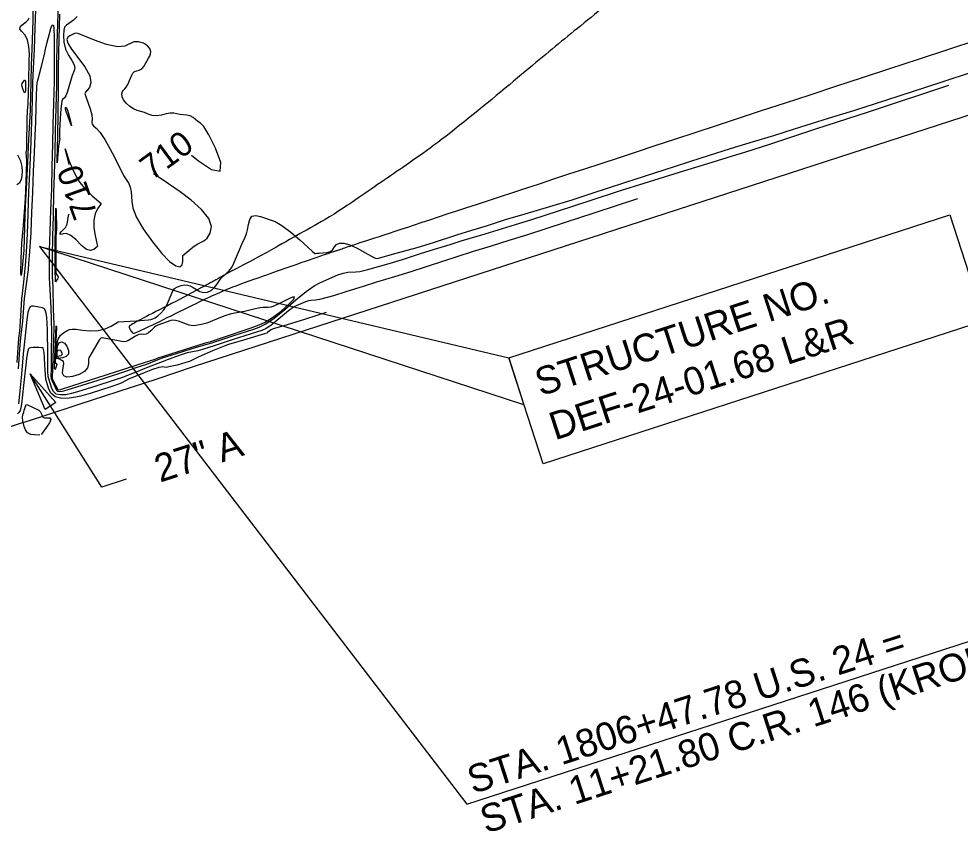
# Model space of a CAD drawing. Extents: x -468541894 to 3393103, y -306086142 to 1227927.
# Drawn here: x 1845797 to 1847065, y 538248 to 539346 of the extents above; entities that cross this region are included whole.
import ezdxf

# ---------------------------------------------------------------- set-up
doc = ezdxf.new("R2010")
doc.units = 0
for name, color, linetype in [('DT_X_Contour_Minor', 7, 'Continuous'), ('Level 14', 7, 'Continuous'), ('Level 19', 7, 'Continuous'), ('Level 25', 7, 'Continuous'), ('Level 40', 7, 'Continuous')]:
    doc.layers.add(name, color=color, linetype=linetype)

msp = doc.modelspace()

# ---------------------------------------------------------------- linework, layer by layer
at = {"layer": 'DT_X_Contour_Minor'}
for points in [[(1845796.1, 539631.5), (1845814.6, 539657.1), (1845822.7, 539667.7), (1845827.1, 539671.5), (1845828.6, 539670.1), (1845828.6, 539666.3), (1845827.1, 539640.6), (1845825.6, 539618.4), (1845823.8, 539591.3), (1845822.3, 539563.4), (1845821.5, 539536.7), (1845820.2, 539505.2), (1845818.8, 539476.1), (1845818.5, 539455), (1845817.9, 539424.5), (1845817.2, 539407), (1845816, 539372.8), (1845815.2, 539345), (1845814.3, 539317.6), (1845813.1, 539283.3), (1845812.5, 539261.9), (1845811.7, 539224.5), (1845811.3, 539214.9)], [(1845849.4, 539368.3), (1845848.6, 539339.2), (1845847.9, 539313.8), (1845847.2, 539285.2), (1845847.1, 539256.6), (1845846.4, 539226.7), (1845845.7, 539194.5), (1845845, 539166.5), (1845844, 539136.2), (1845843.3, 539111.8), (1845842.6, 539080.6), (1845841.7, 539053.3), (1845841.5, 539025.6), (1845841.6, 538998.3), (1845842.3, 538984.9), (1845843, 538954.3), (1845843.5, 538935.1), (1845843.6, 538928.7), (1845843.2, 538915.2), (1845842.3, 538889.5), (1845842.1, 538874.3), (1845841.6, 538862.2), (1845841.9, 538860.4), (1845842.8, 538858.3), (1845848.9, 538846.4), (1845849.4, 538846), (1845850.2, 538846), (1845852.9, 538846.7), (1845869.1, 538851.8), (1845901.8, 538862.4), (1845928.1, 538870.7), (1845957.4, 538880.1), (1845980.1, 538887.6), (1845984.2, 538889.2), (1846010, 538897.4), (1846048, 538909.3), (1846055.2, 538911.5), (1846072.5, 538917.3), (1846106.9, 538928.7), (1846118.2, 538932.7), (1846127.6, 538937), (1846138.6, 538943.5), (1846150.3, 538952.4), (1846160.5, 538961.6), (1846167, 538968.6), (1846168.1, 538971.4), (1846165.2, 538971), (1846160.4, 538968.9), (1846146.2, 538961.7), (1846139.1, 538958.3)], [(1845810.9, 539130.3), (1845812.1, 539159.2), (1845813, 539180.8), (1845814.2, 539208.3), (1845815.1, 539236.4), (1845815.5, 539260), (1845816.3, 539279.4), (1845817.6, 539305.3), (1845818.6, 539334), (1845819.4, 539359.1)], [(1845811.3, 539214.9), (1845809.6, 539183.7), (1845808.1, 539153.2), (1845806.7, 539126.1), (1845805.2, 539093.5), (1845804.3, 539065.8), (1845803.1, 539034.5), (1845800.4, 539006), (1845799.5, 539000.4), (1845799.3, 539003.9), (1845799.8, 539022.7), (1845800.8, 539044), (1845802.7, 539067.8), (1845805.4, 539104.3), (1845806.3, 539126.4), (1845807.1, 539154), (1845807, 539161.5), (1845806.4, 539165.9), (1845806.3, 539167), (1845806.9, 539167.8), (1845807.2, 539170), (1845807.5, 539176), (1845807.9, 539211), (1845808.3, 539222.5), (1845808.9, 539232), (1845809.9, 539261.3), (1845810.6, 539290.2), (1845810.7, 539298.9), (1845810.1, 539308.9), (1845808.1, 539318.1), (1845804.4, 539324.7), (1845800.4, 539329.2), (1845797.8, 539332.5), (1845798.2, 539335.3), (1845800.6, 539338), (1845806.7, 539342.7), (1845809, 539345.1), (1845810.6, 539347.9)], [(1845875.3, 539349.6), (1845870.2, 539344.7), (1845860.6, 539337.8), (1845858.3, 539335.2), (1845857.1, 539331), (1845856.6, 539323.9), (1845857.2, 539315), (1845859.5, 539305.7), (1845863.5, 539297.3), (1845868, 539290.1), (1845871.1, 539284.4), (1845871.8, 539279.8), (1845870.5, 539275.5), (1845868.3, 539270), (1845866, 539262.5), (1845861.8, 539247.3), (1845859.9, 539242.6), (1845858.2, 539240), (1845855.5, 539237.6), (1845854.5, 539235.2), (1845853.5, 539229.3), (1845852.6, 539219), (1845851.3, 539196), (1845851.5, 539186), (1845851.6, 539184.6), (1845850.2, 539175.3), (1845848.1, 539152.3), (1845848.1, 539156.4), (1845849, 539188), (1845849.5, 539218.5), (1845850, 539252.1), (1845850.1, 539281.8), (1845850.4, 539300.1), (1845850.9, 539319.5), (1845852, 539352.7)], [(1845796.2, 538874.3), (1845798.5, 538907.4), (1845799.9, 538920.4), (1845801.7, 538938.8), (1845804.1, 538969.3), (1845805.8, 538982.5), (1845809.4, 539008.1), (1845810.1, 539016.3), (1845811.3, 539032.7), (1845812.4, 539045.3), (1845813.2, 539058.5), (1845814, 539085.7), (1845815.3, 539112.4), (1845816.4, 539141.1), (1845817.5, 539165.5), (1845818.6, 539189.4), (1845819.5, 539207.2), (1845819.9, 539228.2), (1845821, 539255.4), (1845821.9, 539262.4), (1845823.4, 539268.2), (1845824.6, 539272.1), (1845826.7, 539280.7), (1845831.3, 539298.3), (1845832.7, 539305.4), (1845834.2, 539313.2), (1845839.2, 539331.5), (1845839.7, 539333.6), (1845840.7, 539335.9), (1845841.8, 539337.7), (1845842.8, 539338.4), (1845843.3, 539337.5), (1845843.6, 539333.4), (1845844, 539321.3), (1845844.3, 539308.9), (1845844.2, 539293.2), (1845844.2, 539280.8), (1845844.1, 539261.4), (1845843.3, 539232.9), (1845842.5, 539203.5), (1845841.8, 539177.4), (1845841.1, 539147.1), (1845840.4, 539117.2), (1845839.3, 539088.2), (1845838.1, 539059.8), (1845837.5, 539034.3), (1845837.2, 539007.7), (1845837.6, 538997.1), (1845838.9, 538973.3), (1845839.5, 538956.5), (1845840.3, 538940.1), (1845840.7, 538924.8), (1845840, 538894.2), (1845839.9, 538875.7), (1845839.7, 538864), (1845840, 538861.6), (1845840.8, 538859.2), (1845847.1, 538845.5), (1845848.6, 538844.2), (1845851, 538843.7), (1845855.2, 538844.3), (1845861.8, 538846.1), (1845881.8, 538852.3), (1845910.5, 538861.6), (1845942, 538871.7), (1845954.8, 538876.2)], [(1846786.6, 539180.9), (1846814.2, 539189.3), (1846842, 539198), (1846887.9, 539212.3), (1846922.2, 539222.7), (1846965.2, 539236.6), (1847039.8, 539261), (1847127, 539289.7), (1847259.8, 539333.4)], [(1846029.2, 539162.6), (1846038.8, 539154.8), (1846056.4, 539143.4), (1846068.1, 539141.1), (1846068.7, 539152.6), (1846061.6, 539171.9), (1846052.5, 539190.2), (1846045.8, 539201.1), (1846041.3, 539205.8), (1846038, 539208.1), (1846031.4, 539213.3), (1846027.4, 539215.4), (1846022.9, 539216.5), (1846013.5, 539217.3), (1846005.4, 539219.3), (1846000.7, 539219.4), (1845995, 539218.1), (1845988.7, 539216.3), (1845982.3, 539215.4), (1845976.3, 539216.1), (1845970.8, 539218), (1845965.7, 539220), (1845956.1, 539223), (1845951.2, 539225.1), (1845946, 539228.4), (1845941.2, 539232.5), (1845937.6, 539237), (1845935.8, 539241.4), (1845935.5, 539245.2), (1845936.3, 539248.3), (1845937.6, 539250.3), (1845939.4, 539252), (1845941.4, 539254.3), (1845943.4, 539257.8), (1845947.2, 539266.4), (1845948.7, 539270.3), (1845950.4, 539273.3), (1845952.6, 539275.4), (1845955.5, 539276.5), (1845958.9, 539277.3), (1845962.2, 539279), (1845965, 539282.1), (1845971.5, 539293.3), (1845973, 539296.1), (1845974.1, 539299), (1845974.3, 539302.4), (1845973.1, 539306.2), (1845970, 539310.1), (1845964.5, 539313.5), (1845957.9, 539315.6), (1845951.4, 539315.5), (1845939.3, 539309.5), (1845929.5, 539308.6), (1845914.9, 539312), (1845898.7, 539317.8), (1845877.4, 539326.2), (1845873.8, 539327), (1845871.7, 539326.5), (1845868.7, 539325.4), (1845865.4, 539323.7), (1845862.6, 539321.5), (1845861.3, 539318.4), (1845862.5, 539313.5), (1845867.3, 539305.7), (1845885.5, 539281.6), (1845892.3, 539269.5), (1845893.8, 539260.2), (1845891.6, 539253.7), (1845886.6, 539247.4), (1845885.4, 539245.8)], [(1845805.7, 539256.9), (1845805.4, 539249.8), (1845805, 539247.4), (1845804.3, 539246.7), (1845803.1, 539248.5), (1845801.9, 539251.8), (1845801, 539255.2), (1845800.8, 539257.6), (1845801.2, 539259.2), (1845803.2, 539262.3), (1845804.2, 539263.6), (1845805, 539263.8), (1845805.5, 539262.6), (1845805.7, 539260.5), (1845805.7, 539256.9)], [(1845954.8, 538876.2), (1845968.9, 538880.9), (1845982.3, 538886), (1845990.3, 538889.1), (1846001.9, 538892.9), (1846036, 538903.5), (1846056.8, 538909.5), (1846084.9, 538918.9), (1846113.4, 538928.1), (1846120.3, 538930.6), (1846129.3, 538935.1), (1846140.8, 538942.8), (1846155, 538954.4), (1846170.1, 538967.4), (1846183.9, 538978.9), (1846194.7, 538986.4), (1846203.3, 538991), (1846226.7, 539001), (1846233.9, 539003.5), (1846240.1, 539004.6), (1846250.9, 539005.2), (1846256.1, 539005.9), (1846267.1, 539008.6), (1846295.7, 539016.4), (1846313.6, 539021.9), (1846339.3, 539030.3), (1846361.3, 539037.1), (1846377.7, 539042.3), (1846392.6, 539047), (1846424.9, 539056.6), (1846454.2, 539065.4), (1846465.8, 539068.9), (1846488, 539075.9), (1846523.8, 539087.6), (1846566.7, 539101.6), (1846607.6, 539114.8), (1846639.6, 539124.9), (1846687.2, 539139.5), (1846730.9, 539153.2), (1846758.5, 539161.6), (1846775.1, 539166.8), (1846810.1, 539178), (1846870.9, 539197.9), (1846941.9, 539221.2), (1847050, 539256.9)], [(1845885.4, 539245.8), (1845885.8, 539244.2), (1845887.1, 539240.2), (1845892.7, 539225.1), (1845894.9, 539217.1), (1845895.3, 539211.2), (1845895, 539207), (1845895.3, 539204.2), (1845897.3, 539202), (1845900.9, 539198.9), (1845906.1, 539193.2), (1845912.5, 539183.6), (1845919.2, 539171.7), (1845925.5, 539159.8), (1845937.6, 539135.1), (1845944.8, 539124.2), (1845946.6, 539119.3), (1845947.9, 539113.3), (1845948.5, 539106.8), (1845948.7, 539100), (1845950, 539091.5), (1845954.8, 539079.6), (1845964.2, 539063.4), (1845976.5, 539045.7), (1845989.1, 539030), (1845999.8, 539019.2), (1846008, 539013.4), (1846013.5, 539012.2), (1846016.5, 539014.9), (1846017.5, 539019.4), (1846017.7, 539027.4)], [(1845867.4, 539202.3), (1845860.4, 539221.3), (1845859.5, 539224.5), (1845859.3, 539226.2), (1845859.5, 539226.9), (1845860, 539227.2), (1845860.9, 539226.3), (1845862, 539223.4), (1845865.1, 539211.9), (1845867.4, 539202.3)], [(1845857.4, 538881.6), (1845856.9, 538884.3), (1845854.7, 538885.7), (1845851.5, 538887.3), (1845848.8, 538891), (1845847.5, 538898), (1845847.8, 538906.6), (1845849.6, 538914.6), (1845852.9, 538920), (1845856.7, 538923.1), (1845862.5, 538926.5), (1845863.3, 538927.1), (1845864.9, 538927.7), (1845868.2, 538928.1), (1845873.9, 538927.8), (1845882.5, 538926.8), (1845892.9, 538925.9), (1845903.5, 538926.2), (1845913, 538928.6), (1845920.8, 538932.1), (1845930.6, 538937.9), (1845954.8, 538939.4), (1845971.1, 538940.4), (1845974.4, 538940.9), (1845977.2, 538941.8), (1845980.2, 538943.3), (1845983.9, 538945.9), (1845988, 538949.4), (1845992, 538954), (1845995.4, 538959.6), (1845998.3, 538965.6), (1846003.9, 538979.7), (1846006.5, 538982.7), (1846010.5, 538985), (1846015.2, 538986.7), (1846019.9, 538987.5), (1846024, 538987.4), (1846027.6, 538986.3), (1846031.4, 538984.3), (1846035.8, 538981.4), (1846040.7, 538978.7), (1846045.8, 538977.2), (1846051, 538977.9), (1846055.8, 538980.3), (1846060, 538983.9), (1846063.3, 538988), (1846069, 538996.4), (1846072.3, 538999.9), (1846079, 539005.8), (1846081.6, 539008.5), (1846083.9, 539011.9), (1846086.4, 539016.9), (1846092.7, 539031.8), (1846097.5, 539043.3), (1846101.8, 539052.1), (1846103.3, 539056.4), (1846104.7, 539062), (1846105.9, 539069.1), (1846107.7, 539075.9), (1846110.8, 539080.4), (1846115.9, 539081.4), (1846122.2, 539079.9), (1846142.2, 539073), (1846151.2, 539067.6), (1846163, 539058.7), (1846175.5, 539048.2), (1846191.8, 539033.3), (1846195.6, 539029.8), (1846196.5, 539029.8), (1846198.2, 539030.2), (1846201.3, 539030.6), (1846206.1, 539030.7), (1846211.7, 539031.1), (1846216.6, 539032.5), (1846219.7, 539035.4), (1846222, 539038.9), (1846224.6, 539042.1), (1846228.7, 539043.9), (1846234.6, 539043.9), (1846242.6, 539041.6), (1846252.7, 539037), (1846263, 539031.5), (1846276, 539024.2), (1846278.6, 539023.4), (1846281.2, 539023.9), (1846305.2, 539030.3), (1846333.3, 539038), (1846355.3, 539044.8), (1846386.8, 539055.1), (1846407.3, 539061.5), (1846427.1, 539067.5), (1846452.4, 539075.7), (1846478.9, 539083.6), (1846512.1, 539093.5), (1846542.2, 539102.5), (1846569.4, 539111.2), (1846613.5, 539125.5), (1846666.2, 539142.7), (1846716.4, 539159), (1846755.8, 539171.4), (1846786.6, 539180.9)], [(1845864.6, 539150.2), (1845863.5, 539154.2), (1845858.9, 539170.9), (1845864.5, 539154.4), (1845870, 539141), (1845877.4, 539127.5), (1845886.3, 539116.3), (1845895.2, 539107.7), (1845907.7, 539097.6), (1845902.5, 539090), (1845899.4, 539083.5), (1845897.5, 539074.8), (1845897.7, 539064.5), (1845899.2, 539054.2), (1845902.5, 539039.6)], [(1845793.7, 539122.9), (1845798, 539125.7), (1845800.2, 539129.7), (1845801.2, 539134.7), (1845801.6, 539140.6), (1845801.2, 539147.2), (1845799.3, 539154.7), (1845795.4, 539162.7)], [(1845794.5, 538883.1), (1845796.7, 538916), (1845797.7, 538925.5), (1845798.7, 538938.1), (1845800.7, 538968.9), (1845801.8, 538980.1), (1845803.4, 538991.7), (1845805.6, 539013.8), (1845807, 539032.2), (1845808.1, 539055.9), (1845809, 539083.9), (1845810.2, 539113.1), (1845810.9, 539130.3)], [(1846017.7, 539027.4), (1846025.5, 539034.2), (1846031.1, 539038.6), (1846036.8, 539042.5), (1846046.1, 539047.1), (1846050.4, 539050.8), (1846054.4, 539057.2), (1846056.2, 539066.3), (1846052.8, 539077.3), (1846042.9, 539089.5), (1846028.7, 539101.8), (1846013.8, 539113), (1845991, 539128.8), (1845977.9, 539137.5)], [(1846630.4, 539103.8), (1846604.4, 539095.2), (1846571.7, 539084.4), (1846533, 539071.7), (1846481, 539054.8), (1846457, 539047.4), (1846433.3, 539040), (1846407.4, 539032.1), (1846367.8, 539019.4), (1846325, 539005.4), (1846303.1, 538998.7), (1846278.8, 538991.4), (1846262, 538986.1), (1846237.3, 538978.3), (1846220.5, 538973.1), (1846202, 538968), (1846196.2, 538967), (1846190.3, 538966.7), (1846186.9, 538966.1), (1846183, 538964.7), (1846170.3, 538959.3), (1846165.6, 538956.8), (1846159.8, 538952.7), (1846136.4, 538933.1), (1846129.9, 538928.9), (1846124, 538926.1), (1846109.6, 538921.6), (1846084, 538913.7), (1846060, 538905.5), (1846043.9, 538900.3), (1846037.6, 538898.8), (1846023.3, 538895.9), (1846013.8, 538892.9), (1845997.6, 538887.2), (1845989.6, 538884.1), (1845968.8, 538875.6), (1845954.5, 538870.1), (1845946, 538867), (1845936.2, 538862.8), (1845923.9, 538858.6), (1845900.2, 538851.1), (1845875.7, 538843.3), (1845867.6, 538841.2), (1845859.7, 538839.6), (1845852.6, 538839.2), (1845847, 538840.4), (1845843.4, 538843.7), (1845841.2, 538848), (1845836.8, 538861.1), (1845836.2, 538864.2), (1845835.7, 538871.1), (1845835.5, 538893.6), (1845835.1, 538927.5), (1845834.1, 538943.5), (1845833.5, 538949.4), (1845832.7, 538952.1), (1845831.8, 538954.3), (1845831.2, 538955.2), (1845830.1, 538956), (1845828.5, 538956.7), (1845823.3, 538957.8), (1845816.4, 538958.9), (1845813.5, 538958.9), (1845811.7, 538958.1), (1845810.7, 538956.8), (1845809.4, 538953), (1845808.8, 538950.3), (1845807.5, 538940.8), (1845804.7, 538915.1), (1845802.4, 538894.5), (1845800.2, 538867.2), (1845797.5, 538840.4), (1845796.1, 538827.4)], [(1845845.8, 538991.9), (1845845.6, 539010.2), (1845845.7, 539037.9), (1845845.9, 539069.8), (1845846.5, 539090.9), (1845846.7, 539087.8), (1845847.2, 539061.8), (1845846.9, 539058.9), (1845846.6, 539051.8), (1845846.3, 539024.6), (1845846.4, 539005.2), (1845846.7, 539002.5), (1845849.4, 538998.4), (1845849.5, 538997.6), (1845848.6, 538996), (1845845.8, 538991.9)], [(1845902.5, 539039.6), (1845900.4, 539037.6), (1845897.5, 539035.3), (1845893.3, 539033.8), (1845887.7, 539035.2), (1845880.9, 539040.9), (1845873.6, 539048.4), (1845866.7, 539054.4), (1845860.9, 539056.8), (1845856.5, 539056.5), (1845853.6, 539055.6), (1845852.1, 539055.9), (1845852.1, 539057.2), (1845853.6, 539059.2), (1845856.4, 539061.7), (1845859.6, 539065), (1845861.9, 539069.5), (1845863.5, 539081.3), (1845864.5, 539083.4)], [(1846210.8, 538950.6), (1846183.1, 538941.6), (1846158, 538933.7), (1846141, 538928.8), (1846139.4, 538928.4), (1846136.6, 538927.2), (1846134.4, 538925.5), (1846131.9, 538923.4), (1846130.6, 538922.6), (1846127.8, 538921.7), (1846099.3, 538913.2), (1846079.1, 538907.2), (1846073.1, 538904.9), (1846057.7, 538898.7), (1846039.2, 538890.8), (1846026.4, 538884.5), (1846021.6, 538882.9), (1846009.8, 538879.6), (1845998.9, 538877), (1845995.2, 538876.4), (1845993, 538876.5), (1845990.4, 538877.1), (1845988.4, 538876.9), (1845985.4, 538876.3), (1845976.8, 538873.5), (1845965.4, 538869.1), (1845944.4, 538860.4), (1845935.4, 538855.6), (1845932.4, 538854.3), (1845922, 538850.8), (1845892.6, 538841.4), (1845880.1, 538837.7), (1845873.4, 538836.3), (1845864.3, 538835), (1845854.3, 538834.6), (1845845.5, 538836.7), (1845839.7, 538841.8), (1845836.4, 538848.4), (1845833.1, 538860.4), (1845832.4, 538866.8), (1845831.5, 538879.5), (1845831.2, 538889.6), (1845830.5, 538897), (1845829.3, 538902.2), (1845829, 538902.6), (1845827.7, 538902.9), (1845823.7, 538903.1), (1845815.8, 538903.1), (1845812.4, 538902.8), (1845810.4, 538902.2), (1845809.4, 538901.2), (1845808.4, 538896.8), (1845806.9, 538888.5), (1845805.9, 538879.7), (1845803, 538852), (1845800.2, 538827), (1845799.3, 538822.1), (1845798.2, 538818.4), (1845796.7, 538815.7), (1845794.7, 538813.6)], [(1846139.1, 538958.3), (1846136, 538957.4), (1846132.8, 538957.1), (1846125.9, 538957), (1846121.9, 538956.6), (1846113.4, 538954.9), (1846100.5, 538951.9), (1846082.8, 538948.5), (1846074.4, 538946), (1846066.3, 538942.9), (1846054.4, 538937.8), (1846049.9, 538936.2), (1846044.7, 538934.8), (1846034.9, 538932.9), (1846031.5, 538932.6), (1846028.7, 538932.8), (1846026, 538933.4), (1846011.6, 538938.6), (1846007.6, 538939.7), (1846004.1, 538940.1), (1846001.4, 538939.8), (1845983.9, 538933.5), (1845981.3, 538932.1), (1845979.2, 538930.5), (1845974.4, 538925.6), (1845971.3, 538922.9), (1845968.1, 538921.1), (1845965.2, 538920.9), (1845962.1, 538921.2), (1845958.3, 538920.8), (1845953.7, 538918.6), (1845944.3, 538912.8), (1845940.9, 538911.3), (1845937.6, 538911), (1845932.9, 538911.7), (1845908.8, 538916.4), (1845906.9, 538916), (1845905.4, 538914), (1845895.6, 538896.7), (1845890.9, 538889.1), (1845890.4, 538887.3), (1845890.3, 538880.7), (1845889.1, 538875.9), (1845885.2, 538871), (1845877.8, 538866.8), (1845868.9, 538863.9), (1845861.3, 538863.2), (1845857, 538865), (1845855.5, 538868.7), (1845855.8, 538873.3), (1845857.4, 538881.6)], [(1845845.6, 538882), (1845846.9, 538882.1), (1845847.5, 538881.6), (1845847.6, 538880.2), (1845847, 538877.7), (1845845.9, 538875), (1845845, 538873.6), (1845844.5, 538874.5), (1845844.5, 538879.5), (1845845.3, 538900.9), (1845846.8, 538932.6), (1845847.3, 538931.2), (1845847.4, 538929.3), (1845846.8, 538921.3), (1845846.1, 538899.7), (1845845.6, 538882)], [(1845847.1, 538888), (1845847.4, 538896), (1845848, 538901.5), (1845849.3, 538906.5), (1845851.5, 538909.8), (1845854.5, 538910.7), (1845857.9, 538909.1), (1845861.3, 538904.8), (1845863.6, 538899.3), (1845863.4, 538894.2), (1845860.2, 538890.9), (1845855.3, 538889.2), (1845847.1, 538888)], [(1845847.9, 538891), (1845848.2, 538896.4), (1845848.7, 538898.3), (1845849.6, 538899.6), (1845850.8, 538900), (1845852.2, 538899.4), (1845853.5, 538897.7), (1845854.4, 538895.5), (1845854.4, 538893.5), (1845853.1, 538892.2), (1845851.1, 538891.5), (1845847.9, 538891)], [(1845824.8, 538785.2), (1845817.7, 538785.3), (1845812.8, 538786.1), (1845808.4, 538788.2), (1845805.4, 538792), (1845803.6, 538796.7), (1845801.9, 538804.4), (1845801.6, 538808.8), (1845802, 538812.7), (1845803.1, 538816.2), (1845803.7, 538818.6), (1845804.4, 538821), (1845806, 538824.9), (1845806.5, 538825.8), (1845807.2, 538826.3), (1845808.1, 538826.1), (1845823.7, 538818.5), (1845825.8, 538816.6), (1845826.8, 538814.8), (1845827.8, 538810.9), (1845829, 538809.2), (1845831.3, 538808.2), (1845838.4, 538808.2), (1845839.8, 538806.2), (1845837.7, 538801.6), (1845833.8, 538795.6), (1845827.1, 538786.2), (1845827.7, 538786.4)]]:
    msp.add_lwpolyline(points, dxfattribs=at)
at = {"layer": 'Level 14'}
for points in [[(1845828.7, 538810.8), (1845878, 538827), (1845930.3, 538844), (1845983.1, 538861.1), (1846032.1, 538877.7), (1846083.4, 538894.3), (1849141.5, 539887)], [(1845802.2, 538802.2), (1845828.7, 538810.8)], [(1845802.2, 538802.2), (1845743.3, 538782.9), (1845690.4, 538765.7), (1845639.3, 538749.2), (1845588.9, 538733.2), (1845534.6, 538715.9), (1845483.7, 538699.6), (1845433.6, 538683.6), (1845383.7, 538667.8), (1845333.5, 538651.6), (1845283.8, 538635.5), (1845234, 538619.2), (1845182, 538602.3), (1845130.7, 538585.6), (1845079.6, 538569), (1845030.1, 538553.3), (1844978.5, 538536.6), (1844929.9, 538520.7), (1844871.3, 538501.9), (1844825.7, 538486.6), (1844773.7, 538469.7), (1844725.5, 538454.2), (1844675.8, 538437.8), (1844623.1, 538421.1)]]:
    msp.add_lwpolyline(points, dxfattribs=at)
at = {"layer": 'Level 25'}
msp.add_line((1846040.3, 538982.6), (1846008.2, 538965.4), dxfattribs=at)
for points, degree in [([(1846791.2, 539564.7), (1846759.6, 539527.7), (1846755.7, 539523.5), (1846744.7, 539511.5), (1846731.1, 539497.8), (1846716, 539483.2), (1846608.4, 539380.3), (1846534.8, 539322.2), (1846471.7, 539269), (1846358.6, 539175.5), (1846294.4, 539133.1), (1846222, 539082.3), (1846185.1, 539062.3), (1846148.5, 539041.1), (1846113.2, 539021.9), (1846084.1, 539006.6)], 3), ([(1846008.2, 538965.4), (1845992.4, 538957.1), (1845964.3, 538943.2), (1845947.7, 538933.6), (1845945.5, 538932.2), (1845945.2, 538931.3), (1845945, 538929.9), (1845948.8, 538924.1), (1845950, 538922.5), (1845950.9, 538922.6), (1845954.4, 538923), (1845989.4, 538939.7), (1846036.7, 538963.5), (1846075.9, 538982.1), (1846133, 539002.3), (1846233.4, 539037.1), (1846256, 539044.4), (1847268.1, 539377.4)], 3), ([(1846084.6, 539006.9), (1846067.1, 538997.2), (1846052.5, 538989.2), (1846040.3, 538982.6)], 2)]:
    msp.add_open_spline(points, degree=degree, dxfattribs=at)
at = {"layer": 'Level 40'}
for p, q in [((1845824.3, 539039.2), (1846400.4, 538287.4)), ((1845832, 538819.7), (1845811.8, 538867.9)), ((1845811.8, 538867.9), (1845846.5, 538828.9)), ((1845846.5, 538828.9), (1845832, 538819.7)), ((1846400.4, 538287.4), (1847542.5, 538658.2))]:
    msp.add_line(p, q, dxfattribs=at)
for points in [[(1846456.8, 538889.1), (1847051.2, 539082.1), (1847097.5, 538939.4), (1846503.1, 538746.4)], [(1846477.3, 538825.9), (1845824.3, 539039.2), (1846456.8, 538889.1)]]:
    msp.add_lwpolyline(points, close=True, dxfattribs=at)
msp.add_lwpolyline([(1845941.4, 538725.6), (1845908.2, 538714.8), (1845811.8, 538867.9)], dxfattribs=at)

# ---------------------------------------------------------------- texts
at = {"layer": 'Level 19'}
for rotation, p in [(36.4831, (1845975.5, 539127.6)), (109.6923, (1845902.9, 539083.3))]:
    msp.add_text('710', height=33, rotation=rotation, dxfattribs=at).set_placement(p)
at = {"layer": 'Level 40'}
for s, p in [('STRUCTURE NO.', (1846499.8, 538837.3)), ('DEF-24-01.68 L&R', (1846519.1, 538777.9)), ('27" A', (1845986.8, 538720.9)), ('STA. 11+21.80 C.R. 146 (KROUSE RD.)', (1846426, 538247.5)), ('STA. 1806+47.78 U.S. 24 =', (1846408.6, 538301))]:
    msp.add_text(s, height=37.5, rotation=17.9864, dxfattribs=at).set_placement(p)

doc.saveas('drawing.dxf')
